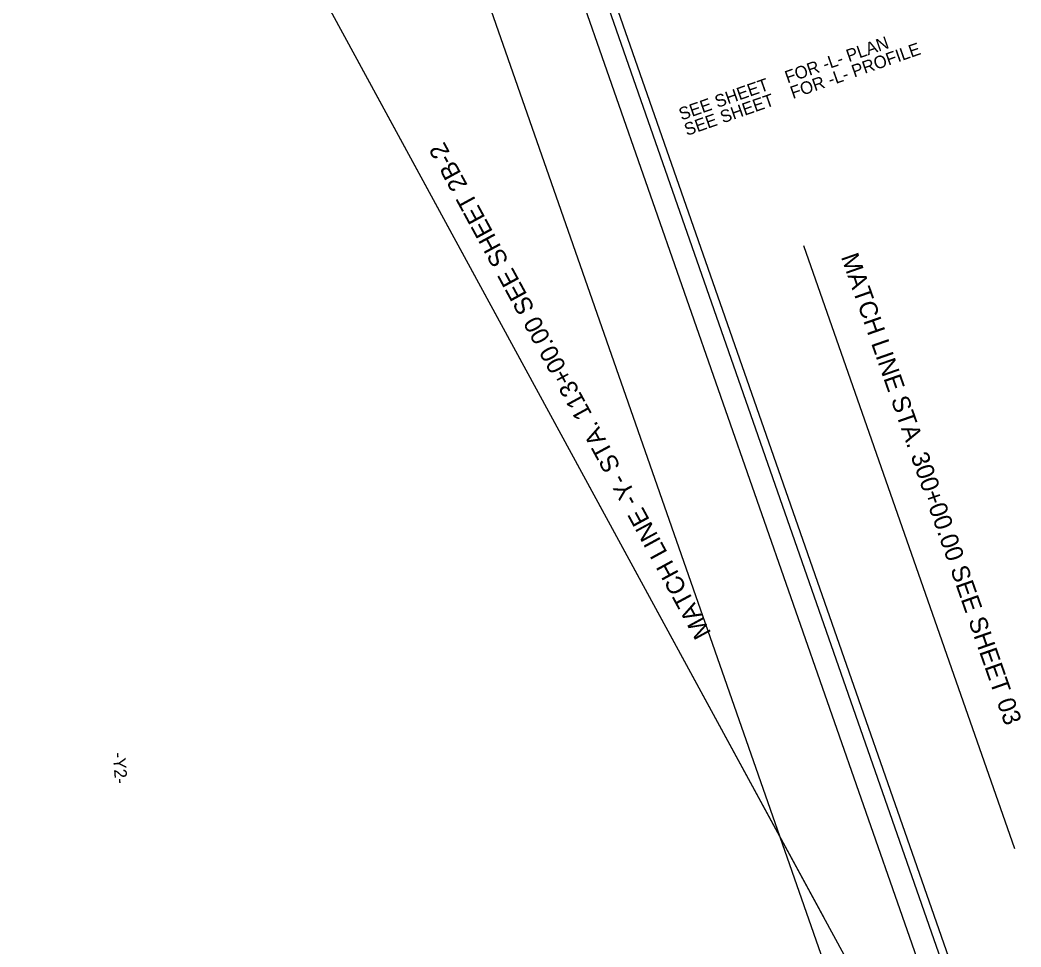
# Model space of a CAD drawing. Extents: x 1721700 to 1723652, y 970581 to 972169.
# Drawn here: x 1723091 to 1723652, y 971251 to 971770 of the extents above; entities that cross this region are included whole.
import ezdxf

# ---------------------------------------------------------------- set-up
doc = ezdxf.new("R2010")
doc.units = 0
for name, color, linetype in [('Matchline', 7, 'Continuous'), ('Matchline Text', 7, 'Continuous'), ('Prop Dimension', 7, 'Continuous'), ('Prop Horizontal Alignment Direction Label', 7, 'Continuous'), ('Sheet Clip Boundary CELL', 7, 'Continuous'), ('Sheet Plan CELL', 7, 'Continuous'), ('Sheet Plot Border Inside CELL', 7, 'Continuous'), ('Sheet Plot Border Outside CELL', 7, 'Continuous')]:
    doc.layers.add(name, color=color, linetype=linetype)

msp = doc.modelspace()

# ---------------------------------------------------------------- linework, layer by layer
at = {"layer": 'Matchline'}
for p, q in [((1723542.04, 971266.56), (1723280.4, 971747.75)), ((1723530.38, 971643.98), (1723648.46, 971305.84))]:
    msp.add_line(p, q, dxfattribs=at)
at = {"layer": 'Sheet Clip Boundary CELL'}
for points in [[(1723600.74, 971158.62), (1723483.33, 971374.55), (1723099.98, 972079.55), (1721911.36, 971664.47), (1722084.53, 971168.86), (1722257.61, 970673.21), (1723579.34, 971134.77)], [(1723600.74, 971158.62), (1723483.33, 971374.55), (1723099.98, 972079.55), (1721911.36, 971664.47), (1722084.53, 971168.86), (1722257.61, 970673.21), (1723579.34, 971134.77)], [(1722257.53, 970673.18), (1723579.27, 971134.74), (1723302.82, 971926.38), (1723124.14, 971863.98), (1723054.41, 972063.64), (1721911.36, 971664.47)]]:
    msp.add_lwpolyline(points, close=True, dxfattribs=at)
at = {"layer": 'Sheet Plan CELL'}
msp.add_lwpolyline([(1723280.32, 972142.53), (1721864.15, 971647.99), (1722210.32, 970656.69), (1723626.47, 971151.23)], close=True, dxfattribs=at)
at = {"layer": 'Sheet Plot Border Inside CELL'}
msp.add_lwpolyline([(1722066.24, 970603.72), (1723639.08, 971152.98), (1723291.28, 972148.99), (1721718.43, 971599.74)], close=True, dxfattribs=at)
at = {"layer": 'Sheet Plot Border Outside CELL'}
msp.add_lwpolyline([(1722060.57, 970580.55), (1723649.94, 971135.58), (1723288.94, 972169.36), (1721699.56, 971614.33)], close=True, dxfattribs=at)

# ---------------------------------------------------------------- texts
at = {"layer": 'Matchline Text'}
for s, rotation, p in [('MATCH LINE -Y- STA. 113+00.00 SEE SHEET 2B-2', 118.5349, (1723478.76, 971426.73)), ('MATCH LINE STA. 300+00.00 SEE SHEET 03', 289.2988, (1723551.15, 971637.59))]:
    msp.add_text(s, height=10, rotation=rotation, dxfattribs=at).set_placement(p)
at = {"layer": 'Prop Dimension'}
for s, p in [('SEE SHEET    FOR -L- PLAN ', (1723461.9, 971713.99)), ('SEE SHEET    FOR -L- PROFILE', (1723464.92, 971705.33))]:
    msp.add_text(s, height=7, rotation=19.2497, dxfattribs=at).set_placement(p)
at = {"layer": 'Prop Horizontal Alignment Direction Label'}
msp.add_text('-Y2-', height=7, rotation=274.5198, dxfattribs=at).set_placement((1723143.13, 971359.55))

doc.saveas('drawing.dxf')
